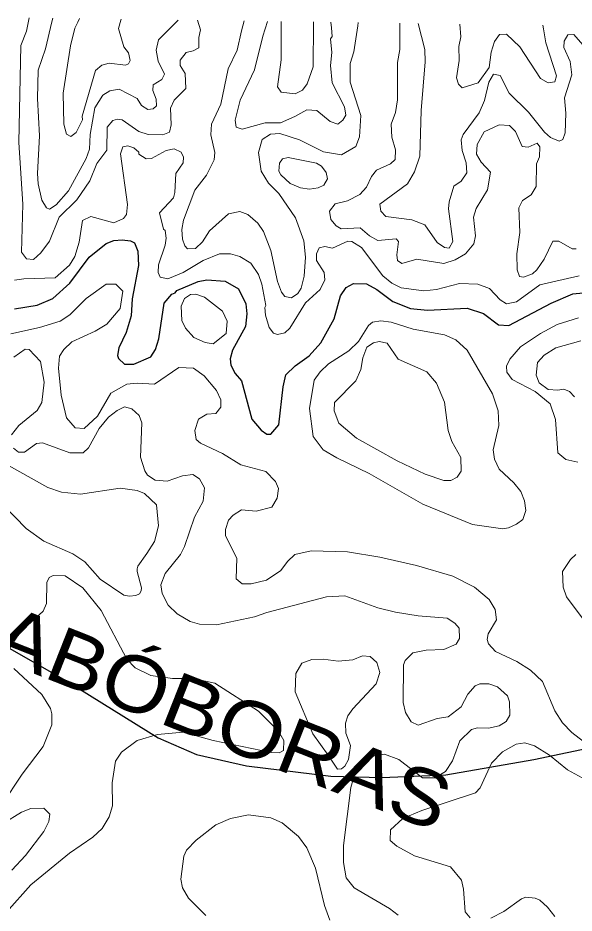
# Model space of a CAD drawing. Extents: x 763.2 to 816.8, y 7896.5 to 7952.7.
# Drawn here: x 774.248 to 776.64, y 7948.665 to 7952.514 of the extents above; entities that cross this region are included whole.
import ezdxf
from ezdxf.enums import TextEntityAlignment as Align

# ---------------------------------------------------------------- set-up
doc = ezdxf.new("R2010")
doc.units = 0
doc.header["$LTSCALE"] = 0.064
for name, color, linetype, lineweight in [('1', 7, 'Continuous', 25), ('2', 7, 'Continuous', 13), ('26', 7, 'Continuous', 25)]:
    doc.layers.add(name, color=color, linetype=linetype, lineweight=lineweight)

msp = doc.modelspace()

# ---------------------------------------------------------------- linework, layer by layer
at = {"layer": '1'}
for points in [[(774.2339, 7951.2633), (774.3307, 7951.2787), (774.398, 7951.307), (774.4715, 7951.3737), (774.5546, 7951.4846), (774.628, 7951.5442), (774.661, 7951.5566), (774.6964, 7951.5599), (774.7332, 7951.5549), (774.7492, 7951.5466), (774.7641, 7951.5112), (774.7677, 7951.4492)], [(774.7677, 7951.4492), (774.74, 7951.3061), (774.7349, 7951.233), (774.7138, 7951.1614), (774.6824, 7951.0949), (774.676, 7951.0628)], [(774.676, 7951.0628), (774.6812, 7951.05), (774.7072, 7951.0246), (774.7464, 7951.0257), (774.8201, 7951.057), (774.8398, 7951.0877), (774.8548, 7951.1344), (774.878, 7951.287), (774.9104, 7951.3261), (774.9253, 7951.3319), (774.9312, 7951.3416), (775.0242, 7951.3802), (775.0602, 7951.3871), (775.1396, 7951.3826), (775.1976, 7951.3484), (775.228, 7951.285), (775.2329, 7951.2421), (775.2277, 7951.1871), (775.1705, 7951.085), (775.1617, 7951.0476), (775.1636, 7951.0206), (775.1827, 7950.9848), (775.2094, 7950.9537), (775.254, 7950.7883), (775.2943, 7950.7418), (775.3184, 7950.7238), (775.3365, 7950.7235), (775.3707, 7950.7638), (775.3892, 7950.9281), (775.4007, 7950.9797), (775.44, 7951.0176), (775.5011, 7951.0609), (775.5517, 7951.1164), (775.6077, 7951.2206), (775.6361, 7951.319), (775.6596, 7951.3548), (775.6914, 7951.3724), (775.7471, 7951.3709), (775.7916, 7951.3463), (775.8613, 7951.2951), (775.9362, 7951.2643), (776.0103, 7951.2577), (776.1803, 7951.2656), (776.2511, 7951.2431), (776.3153, 7951.1938), (776.3596, 7951.192), (776.541, 7951.288), (776.6349, 7951.3277), (776.7095, 7951.3347)]]:
    msp.add_lwpolyline(points, dxfattribs=at)
at = {"layer": '2'}
for points in [[(774.2965, 7952.5138), (774.2936, 7952.4996), (774.2847, 7952.4563), (774.2617, 7952.3958), (774.2519, 7951.9778), (774.2698, 7951.7128), (774.2633, 7951.5071), (774.2859, 7951.4784), (774.3162, 7951.4746), (774.3475, 7951.5031), (774.3848, 7951.5535), (774.4264, 7951.6576), (774.5019, 7951.7315), (774.5579, 7951.8127), (774.5882, 7951.8876), (774.6309, 7951.9457), (774.6316, 7952.0442), (774.6563, 7952.0726), (774.6774, 7952.0791), (774.697, 7952.0759), (774.768, 7952.026), (774.8079, 7952.0132), (774.8721, 7952.0113), (774.901, 7952.0226), (774.9074, 7952.0547), (774.9046, 7952.1258), (774.9208, 7952.1598), (774.97, 7952.2104), (774.9683, 7952.2742), (774.9468, 7952.3093), (774.9455, 7952.3318), (774.9723, 7952.3652), (775.0027, 7952.3719), (775.0259, 7952.3848), (775.026, 7952.4294), (775.0337, 7952.4622), (775.0204, 7952.5034)], [(774.9377, 7952.5046), (774.8523, 7952.4197), (774.8436, 7952.375), (774.8517, 7952.3277), (774.8792, 7952.2724), (774.867, 7952.2496), (774.8301, 7952.2257), (774.8286, 7952.202), (774.8431, 7952.1638), (774.8446, 7952.1356), (774.8295, 7952.1226), (774.8071, 7952.1197), (774.7796, 7952.1373), (774.7618, 7952.1671), (774.6839, 7952.2074), (774.6439, 7952.2005), (774.613, 7952.1822), (774.5789, 7952.127), (774.5591, 7952.0119), (774.5556, 7951.9496), (774.5423, 7951.9095), (774.4661, 7951.7708), (774.4132, 7951.7101), (774.3838, 7951.6915), (774.3721, 7951.6966), (774.3517, 7951.73), (774.3354, 7951.7998), (774.3323, 7951.8443), (774.342, 7952.0069), (774.3323, 7952.1671), (774.3357, 7952.2887), (774.3669, 7952.3808), (774.3948, 7952.4968), (774.3985, 7952.5123)], [(774.514, 7952.5107), (774.5061, 7952.4948), (774.4936, 7952.4697), (774.4739, 7952.3939), (774.4424, 7952.1901), (774.4462, 7952.0575), (774.4577, 7952.0134), (774.4758, 7952.004), (774.4986, 7952.021), (774.526, 7952.0753), (774.5249, 7952.0913), (774.5826, 7952.2882), (774.61, 7952.3108), (774.6412, 7952.3191), (774.7106, 7952.3099), (774.7244, 7952.3161), (774.7318, 7952.3309), (774.7247, 7952.3639), (774.7036, 7952.3892), (774.6808, 7952.4688), (774.6906, 7952.5034), (774.6919, 7952.5081)], [(775.2207, 7952.5005), (775.2104, 7952.4576), (775.1906, 7952.3749), (775.1525, 7952.2946), (775.1209, 7952.1428), (775.0807, 7952.057), (775.0784, 7952.0105), (775.0948, 7951.9358), (775.093, 7951.9036), (775.059, 7951.8383), (775.0086, 7951.7732), (774.9603, 7951.6445), (774.9536, 7951.6037), (774.9557, 7951.5618), (774.966, 7951.5334), (774.9777, 7951.5212), (775.012, 7951.5224), (775.0419, 7951.5516), (775.0729, 7951.5988), (775.1534, 7951.672), (775.2031, 7951.6813), (775.2367, 7951.668), (775.2805, 7951.6307), (775.3048, 7951.5951), (775.3358, 7951.5145), (775.3653, 7951.3799), (775.382, 7951.3345), (775.3967, 7951.3166), (775.4245, 7951.3102), (775.4519, 7951.3291), (775.466, 7951.3516), (775.4791, 7951.4033), (775.4844, 7951.4849), (775.4775, 7951.5558), (775.4424, 7951.6549), (775.3707, 7951.7589), (775.3262, 7951.8038), (775.2948, 7951.8555), (775.2823, 7951.935), (775.2981, 7951.9907), (775.3347, 7952.0134), (775.3742, 7952.0168), (775.4591, 7951.9891), (775.5628, 7951.9384), (775.6401, 7951.9251), (775.701, 7951.9612), (775.7176, 7952.0028), (775.7226, 7952.0944), (775.677, 7952.2373), (775.6766, 7952.3182), (775.6931, 7952.3676), (775.7096, 7952.4804), (775.7115, 7952.4934)], [(775.594, 7952.4951), (775.5964, 7952.4705), (775.6, 7952.4336), (775.5928, 7952.4241), (775.5978, 7952.3648), (775.5927, 7952.3095), (775.5996, 7952.2349), (775.6528, 7952.1317), (775.6582, 7952.0954), (775.645, 7952.074), (775.6236, 7952.0564), (775.5912, 7952.0679), (775.534, 7952.1151), (775.4906, 7952.1187), (775.4399, 7952.0893), (775.3769, 7952.0629), (775.3111, 7952.0627), (775.2127, 7952.0351), (775.1872, 7952.0435), (775.1821, 7952.0746), (775.2043, 7952.16), (775.2655, 7952.2907), (775.3018, 7952.4353), (775.3218, 7952.499)], [(775.3809, 7952.4982), (775.3809, 7952.466), (775.3807, 7952.3334), (775.3648, 7952.2171), (775.3811, 7952.1946), (775.441, 7952.1879), (775.4726, 7952.2031), (775.4921, 7952.2303), (775.5183, 7952.3041), (775.5189, 7952.487), (775.5189, 7952.4962)], [(775.8905, 7952.4908), (775.8902, 7952.3775), (775.8804, 7952.3224), (775.8803, 7952.1617), (775.8721, 7952.1073), (775.8541, 7952.0566), (775.8565, 7952.0005), (775.872, 7951.9469), (775.8703, 7951.9044), (775.8511, 7951.8864), (775.7906, 7951.8594), (775.7687, 7951.8321), (775.7471, 7951.7855), (775.7193, 7951.7542), (775.6654, 7951.7272), (775.6122, 7951.7139), (775.5882, 7951.6823), (775.5945, 7951.6474), (775.6163, 7951.6204), (775.6384, 7951.607), (775.7207, 7951.6107), (775.7606, 7951.5764), (775.7958, 7951.557), (775.8746, 7951.5639), (775.8851, 7951.552), (775.8772, 7951.4954), (775.8804, 7951.4706), (775.8996, 7951.4585), (775.9645, 7951.4761), (776.0796, 7951.4583), (776.129, 7951.4739), (776.1731, 7951.4999), (776.2089, 7951.542), (776.2155, 7951.5762), (776.2075, 7951.657), (776.2193, 7951.6937), (776.2679, 7951.7747), (776.2806, 7951.8499), (776.2409, 7951.8932), (776.2199, 7951.9279), (776.2231, 7951.969), (776.2529, 7952.0234), (776.3175, 7952.0547), (776.3629, 7952.0512), (776.3888, 7952.025), (776.4164, 7951.9613), (776.4422, 7951.958), (776.4812, 7951.9754), (776.4932, 7951.9602), (776.4916, 7951.9159), (776.4787, 7951.887), (776.4768, 7951.7893), (776.4551, 7951.7525), (776.4185, 7951.7281), (776.4031, 7951.6979), (776.4062, 7951.5912), (776.3932, 7951.4992), (776.3949, 7951.4302), (776.4053, 7951.4019), (776.422, 7951.399), (776.4614, 7951.4135), (776.4802, 7951.4304), (776.5114, 7951.4763), (776.5485, 7951.5532), (776.5739, 7951.5532), (776.6313, 7951.5206), (776.6493, 7951.5208)], [(776.7676, 7952.2955), (776.6383, 7952.4426), (776.6129, 7952.4415), (776.598, 7952.4131), (776.5954, 7952.3863), (776.6234, 7952.3269), (776.6298, 7952.2696), (776.599, 7952.1702), (776.605, 7952.104), (776.6015, 7952.0203), (776.5919, 7951.9911), (776.5755, 7951.9845), (776.5382, 7951.9993), (776.5129, 7952.0221), (776.4447, 7952.1085), (776.3608, 7952.1905), (776.3225, 7952.2661), (776.294, 7952.2722), (776.2736, 7952.2377), (776.2548, 7952.1584), (776.232, 7952.1061), (776.1632, 7952.0118), (776.155, 7951.9889), (776.1581, 7951.9436), (776.176, 7951.891), (776.1795, 7951.8474), (776.1551, 7951.8123), (776.1235, 7951.791), (776.1023, 7951.7227), (776.0994, 7951.6923), (776.1187, 7951.5529), (776.1031, 7951.524), (776.0833, 7951.5262), (776.0515, 7951.5485), (775.9978, 7951.6243), (775.9428, 7951.6454), (775.831, 7951.6599), (775.8085, 7951.6828), (775.8051, 7951.7126), (775.9241, 7951.8011), (775.9545, 7951.8516), (775.9772, 7951.92), (775.9823, 7952.1154), (776.0003, 7952.3249), (775.9984, 7952.3783), (775.9695, 7952.4896)], [(776.1489, 7952.487), (776.153, 7952.4327), (776.145, 7952.3902), (776.1466, 7952.3309), (776.1338, 7952.2558), (776.1432, 7952.2295), (776.1591, 7952.2129), (776.2279, 7952.2353), (776.2746, 7952.3004), (776.2831, 7952.3669), (776.298, 7952.4129), (776.3194, 7952.442), (776.3492, 7952.4435), (776.4067, 7952.3893), (776.4955, 7952.2533), (776.5281, 7952.2341), (776.5574, 7952.2393), (776.5639, 7952.2651), (776.5179, 7952.4071), (776.5083, 7952.4672), (776.506, 7952.4819)], [(775.5683, 7951.5317), (775.5435, 7951.5249), (775.5322, 7951.4999), (775.532, 7951.4709), (775.5649, 7951.419), (775.568, 7951.3882), (775.5484, 7951.3454), (775.4858, 7951.2883), (775.4174, 7951.1792), (775.396, 7951.16), (775.365, 7951.1525), (775.3479, 7951.1579), (775.3293, 7951.1823), (775.313, 7951.2353), (775.3102, 7951.2692), (775.315, 7951.2769), (775.2972, 7951.3696), (775.2823, 7951.4099), (775.2504, 7951.46), (775.2033, 7951.4877), (775.1624, 7951.4993), (775.1157, 7951.4994), (775.0455, 7951.4712), (774.9588, 7951.4197), (774.8928, 7951.3924), (774.8597, 7951.3998), (774.8517, 7951.4185), (774.8532, 7951.4526), (774.8822, 7951.5365), (774.8862, 7951.5671), (774.8811, 7951.6004), (774.8746, 7951.6053), (774.8566, 7951.6757), (774.9169, 7951.7401), (774.9239, 7951.7628), (774.9273, 7951.8443), (774.9589, 7951.8914), (774.96, 7951.9156), (774.95, 7951.9361), (774.9199, 7951.951), (774.8864, 7951.9439), (774.8233, 7951.909), (774.8, 7951.9085), (774.7684, 7951.928), (774.7687, 7951.9366), (774.7468, 7951.9557), (774.7207, 7951.9643), (774.699, 7951.9591), (774.689, 7951.9289), (774.7201, 7951.7122), (774.7148, 7951.668), (774.7028, 7951.6516), (774.6616, 7951.6327), (774.5625, 7951.6602), (774.5267, 7951.6422), (774.5115, 7951.5492), (774.493, 7951.4887), (774.4707, 7951.4506), (774.409, 7951.3965), (774.2738, 7951.3924), (774.2336, 7951.3858)], [(775.8171, 7951.405), (775.7259, 7951.527), (775.6846, 7951.5527), (775.6676, 7951.5533), (775.6007, 7951.5241), (775.5683, 7951.5317)], [(776.6614, 7951.4052), (776.4929, 7951.3663), (776.3918, 7951.2933), (776.3498, 7951.284), (776.3229, 7951.3012), (776.276, 7951.3498), (776.2258, 7951.3693), (776.1473, 7951.3726), (776.049, 7951.3459), (775.9945, 7951.34), (775.8971, 7951.3532), (775.857, 7951.3736), (775.8171, 7951.405)], [(774.2176, 7951.1554), (774.3412, 7951.1827), (774.4295, 7951.2093), (774.4714, 7951.2372), (774.5415, 7951.3074), (774.6283, 7951.3691), (774.6696, 7951.3693), (774.6999, 7951.3384), (774.6877, 7951.2639), (774.6302, 7951.1974), (774.5801, 7951.1664), (774.4803, 7951.1211), (774.4457, 7951.0883), (774.4278, 7951.0597), (774.4227, 7951.0081), (774.4342, 7950.8918), (774.4573, 7950.7946), (774.4947, 7950.7519), (774.5338, 7950.7486), (774.5903, 7950.8012), (774.6479, 7950.9008), (774.7175, 7950.9389), (774.7613, 7950.9438), (774.8355, 7950.9393), (774.9405, 7951.0109), (775.0028, 7951.0076), (775.0493, 7950.9744), (775.103, 7950.9123), (775.1211, 7950.8724), (775.1211, 7950.8396), (775.0995, 7950.8127), (775.0614, 7950.8103), (775.0257, 7950.7887), (775.0094, 7950.7393), (775.0146, 7950.7008), (775.0334, 7950.6853), (775.1277, 7950.6413), (775.2073, 7950.5919), (775.314, 7950.5642), (775.3557, 7950.5202), (775.369, 7950.4901), (775.3638, 7950.4494), (775.3403, 7950.411), (775.2731, 7950.3933), (775.2104, 7950.3993), (775.1744, 7950.376), (775.1546, 7950.3542), (775.1412, 7950.314), (775.1409, 7950.2873), (775.1902, 7950.1904), (775.1868, 7950.1027), (775.2132, 7950.0812), (775.2519, 7950.081), (775.3177, 7950.0971), (775.3795, 7950.1374), (775.4078, 7950.1765), (775.4397, 7950.2068), (775.509, 7950.2222), (775.666, 7950.2189), (775.8042, 7950.196), (775.9619, 7950.1599), (776.119, 7950.1142), (776.2117, 7950.0665), (776.2752, 7950.0129), (776.3004, 7949.9705), (776.3058, 7949.9252), (776.2709, 7949.8657), (776.2668, 7949.842), (776.2717, 7949.823), (776.3025, 7949.7895), (776.3937, 7949.747), (776.4529, 7949.7091), (776.5039, 7949.6613), (776.5567, 7949.535), (776.5906, 7949.4832), (776.6309, 7949.4422), (776.7185, 7949.3742)], [(776.6588, 7951.2245), (776.568, 7951.1953), (776.496, 7951.1576), (776.4097, 7951.0998), (776.3632, 7951.0465), (776.349, 7951.016), (776.3505, 7950.9907), (776.3735, 7950.9588), (776.472, 7950.9075), (776.5375, 7950.8549), (776.5605, 7950.7866), (776.5701, 7950.6432), (776.6042, 7950.6149), (776.656, 7950.6037)], [(776.6686, 7951.1259), (776.5618, 7951.0949), (776.5119, 7951.0637), (776.4823, 7951.0329), (776.4771, 7950.9781), (776.4896, 7950.9447), (776.5286, 7950.9159), (776.57, 7950.9126), (776.5956, 7950.9172), (776.6203, 7950.9069), (776.6422, 7950.8852)], [(774.2312, 7951.0547), (774.2792, 7951.0895), (774.2965, 7951.0879), (774.345, 7951.037), (774.3616, 7950.947), (774.3515, 7950.861), (774.3306, 7950.8258), (774.253, 7950.7608), (774.2209, 7950.7216)], [(774.2293, 7950.6637), (774.2517, 7950.6463), (774.2766, 7950.6467), (774.3278, 7950.6833), (774.3541, 7950.6874), (774.4723, 7950.6433), (774.5288, 7950.6432), (774.5524, 7950.666), (774.5978, 7950.7486), (774.638, 7950.7974), (774.6748, 7950.8257), (774.7073, 7950.8412), (774.7389, 7950.8329), (774.7696, 7950.8049), (774.7808, 7950.7728), (774.7761, 7950.6257), (774.7939, 7950.5664), (774.8055, 7950.5479), (774.8384, 7950.5268), (774.8909, 7950.5214), (774.9568, 7950.5443), (775, 7950.5506), (775.0297, 7950.5323), (775.0502, 7950.4936), (775.045, 7950.4362)], [(774.0143, 7950.6972), (774.377, 7950.4943), (774.4352, 7950.4744), (774.5177, 7950.4656), (774.6879, 7950.4916), (774.7609, 7950.4816), (774.7926, 7950.4685), (774.8449, 7950.4203), (774.8532, 7950.3298), (774.836, 7950.2621), (774.8027, 7950.2105), (774.7638, 7950.1566), (774.7616, 7950.1456), (774.7617, 7950.1341), (774.7806, 7950.0638), (774.7791, 7950.0505), (774.7713, 7950.0377), (774.755, 7950.0298), (774.7289, 7950.027), (774.7044, 7950.0316), (774.6024, 7950.1012), (774.5357, 7950.175), (774.485, 7950.209), (774.3596, 7950.2638), (774.2834, 7950.3185), (774.1865, 7950.4189)], [(775.045, 7950.4362), (775.0076, 7950.3676), (774.9651, 7950.241), (774.9476, 7950.2064), (774.8812, 7950.1253), (774.8632, 7950.076)], [(776.647, 7950.2062), (776.6244, 7950.1856), (776.5904, 7950.1344), (776.5933, 7950.066), (776.6071, 7950.0252), (776.7858, 7949.7867)], [(774.1992, 7948.6692), (774.3038, 7948.787), (774.4704, 7948.9223), (774.571, 7948.992), (774.6104, 7949.0282), (774.6408, 7949.0795), (774.6558, 7949.1255), (774.6532, 7949.2258), (774.6677, 7949.3177), (774.6944, 7949.3567), (774.7609, 7949.4076), (774.8484, 7949.4334), (774.9585, 7949.4432), (775.0882, 7949.4072), (775.3375, 7949.3553), (775.3724, 7949.3545), (775.3908, 7949.3642), (775.3913, 7949.4072), (775.3696, 7949.4478), (775.2827, 7949.5331), (775.0954, 7949.6533), (775.0021, 7949.6732), (774.9132, 7949.6731), (774.8194, 7949.6865), (774.753, 7949.7194), (774.7167, 7949.7561), (774.6059, 7949.9662), (774.5278, 7950.0628), (774.4513, 7950.115), (774.3998, 7950.1168), (774.383, 7950.1078), (774.3735, 7950.0858), (774.3718, 7949.9954), (774.3569, 7949.9633), (774.2562, 7949.8716), (774.2111, 7949.8017)], [(774.8632, 7950.076), (774.8683, 7950.0392), (774.8949, 7949.9885), (774.9338, 7949.9512), (774.989, 7949.9186), (775.0298, 7949.9068), (775.1028, 7949.9037), (775.2664, 7949.9381), (775.319, 7949.9577), (775.5748, 7950.0249), (775.6543, 7950.0284), (775.7956, 7949.9772), (775.8715, 7949.9582), (775.9699, 7949.9437), (776.0946, 7949.9327), (776.1278, 7949.9122), (776.1463, 7949.89), (776.1479, 7949.8456), (776.1323, 7949.8206), (776.0801, 7949.7984), (776.0047, 7949.7948), (775.9469, 7949.7836), (775.9134, 7949.7506), (775.9067, 7949.7326), (775.9051, 7949.5699), (775.9152, 7949.5273), (775.9396, 7949.4879), (775.9697, 7949.4729), (776.0507, 7949.5021), (776.0992, 7949.5086), (776.1543, 7949.5512), (776.1832, 7949.6066), (776.2151, 7949.6416), (776.2351, 7949.6502), (776.2741, 7949.6503), (776.311, 7949.6372), (776.3536, 7949.5987), (776.3619, 7949.5738), (776.3634, 7949.5163), (776.3485, 7949.489), (776.3184, 7949.4695), (776.2722, 7949.4599), (776.2244, 7949.4615), (776.199, 7949.4542), (776.1493, 7949.4058), (776.117, 7949.32), (776.0871, 7949.2738), (776.0415, 7949.2471), (775.988, 7949.2461), (775.8866, 7949.3257), (775.8252, 7949.3477), (775.7821, 7949.3411), (775.7424, 7949.3183), (775.6968, 7949.2647), (775.6802, 7949.2057), (775.6487, 7948.9551), (775.6487, 7948.8829), (775.6596, 7948.817), (775.6944, 7948.773), (775.8469, 7948.6844), (775.8836, 7948.656)], [(774.2309, 7949.7172), (774.3508, 7949.6054), (774.3879, 7949.5442), (774.3949, 7949.5215), (774.3947, 7949.4739), (774.3566, 7949.3818), (774.2673, 7949.2629), (774.1787, 7949.1307)], [(776.69, 7949.2387), (776.6118, 7949.2806), (776.5338, 7949.3434), (776.4694, 7949.3837), (776.4288, 7949.3972), (776.3905, 7949.3907), (776.3328, 7949.3577), (776.2856, 7949.3096), (776.236, 7949.2031), (776.2163, 7949.1827), (775.985, 7949.1061)], [(774.2222, 7948.85), (774.2818, 7948.913), (774.3602, 7949.0153), (774.3819, 7949.0584), (774.3863, 7949.0908), (774.3604, 7949.1158), (774.3034, 7949.1146), (774.2646, 7949.0987), (774.1849, 7949.0508)], [(775.985, 7949.1061), (775.9039, 7949.0715), (775.8512, 7949.023), (775.8494, 7948.9769), (775.8773, 7948.9529), (775.9534, 7948.9106)], [(775.5894, 7948.6351), (775.567, 7948.6975), (775.5281, 7948.8579), (775.4907, 7948.9453), (775.4546, 7948.9946), (775.3854, 7949.0527), (775.336, 7949.0746), (775.2394, 7949.0882), (775.1621, 7949.0722), (775.1002, 7949.0446), (775.0148, 7948.9786), (774.9738, 7948.935), (774.9625, 7948.9098), (774.9487, 7948.8112), (774.9565, 7948.7741), (774.9815, 7948.7298), (775.0565, 7948.655)], [(775.9534, 7948.9106), (776.1091, 7948.8636), (776.1563, 7948.8073), (776.1647, 7948.7685), (776.1711, 7948.6702), (776.1925, 7948.6441)], [(776.2822, 7948.6432), (776.3384, 7948.6712), (776.4145, 7948.7266), (776.4325, 7948.7332), (776.472, 7948.7299), (776.4926, 7948.7212), (776.5262, 7948.6908), (776.5566, 7948.6497)]]:
    msp.add_lwpolyline(points, dxfattribs=at)
for points in [[(775.4639, 7951.7835), (775.4198, 7951.802), (775.3792, 7951.8395), (775.3711, 7951.8555), (775.3737, 7951.8893), (775.3864, 7951.9085), (775.4109, 7951.9132), (775.532, 7951.8887), (775.5537, 7951.8768), (775.5743, 7951.8497), (775.5797, 7951.822), (775.5642, 7951.7949), (775.5401, 7951.7838), (775.5019, 7951.777)], [(774.9694, 7951.1802), (774.9536, 7951.2124), (774.9503, 7951.2746), (774.9648, 7951.3078), (774.9905, 7951.325), (775.0131, 7951.3263), (775.0503, 7951.3133), (775.1286, 7951.2526), (775.1488, 7951.21), (775.1439, 7951.1575), (775.0884, 7951.1131), (775.0536, 7951.1176), (775.0052, 7951.1394)], [(776.3159, 7950.7611), (776.3141, 7950.8246), (776.2895, 7950.8977), (776.1798, 7951.085), (776.1317, 7951.1294), (776.0835, 7951.151), (775.9476, 7951.1751), (775.8541, 7951.205), (775.8088, 7951.2115), (775.7733, 7951.2053), (775.7556, 7951.1917), (775.7129, 7951.1219), (775.6709, 7951.083), (775.5835, 7951.0265), (775.5478, 7950.9924), (775.5223, 7950.9561), (775.5026, 7950.8352), (775.5185, 7950.7136), (775.561, 7950.6567), (775.6193, 7950.6224), (775.7594, 7950.5555), (775.9902, 7950.4237), (776.2031, 7950.3355), (776.3333, 7950.3177), (776.3584, 7950.3212), (776.3931, 7950.3366), (776.4193, 7950.3575), (776.4319, 7950.3959), (776.4262, 7950.4369), (776.4108, 7950.4776), (776.381, 7950.5153), (776.3183, 7950.5735), (776.2974, 7950.6164), (776.2927, 7950.6563)], [(776.083, 7950.8622), (776.0483, 7950.9431), (776.0074, 7950.9925), (775.8829, 7951.0473), (775.8362, 7951.1157), (775.8026, 7951.1226), (775.7781, 7951.1175), (775.7493, 7951.098), (775.7311, 7951.0529), (775.7224, 7951.0023), (775.7011, 7950.9537), (775.6094, 7950.8606), (775.6077, 7950.8242), (775.6288, 7950.7711), (775.7051, 7950.7074), (775.8798, 7950.6088), (775.9994, 7950.5524), (776.0803, 7950.525), (776.11, 7950.5247), (776.1376, 7950.5386), (776.1541, 7950.5644), (776.1533, 7950.6236), (776.1144, 7950.6926), (776.099, 7950.7399)], [(775.6573, 7949.4816), (775.667, 7949.5137), (775.6883, 7949.5436), (775.7896, 7949.6512), (775.8048, 7949.6988), (775.7915, 7949.7424), (775.7625, 7949.7681), (775.7299, 7949.7705), (775.6884, 7949.754), (775.626, 7949.7475), (775.5609, 7949.7571), (775.5123, 7949.7555), (775.4697, 7949.7389), (775.4433, 7949.6947), (775.4402, 7949.6167), (775.516, 7949.4355), (775.5829, 7949.3446), (775.623, 7949.284), (775.6397, 7949.2852), (775.6538, 7949.2962), (775.6705, 7949.3255), (775.6782, 7949.3852), (775.6585, 7949.439)]]:
    msp.add_lwpolyline(points, close=True, dxfattribs=at)
at = {"layer": '26'}
msp.add_lwpolyline([(771.0421, 7950.2756), (771.5707, 7950.4081), (771.8675, 7950.4081), (772.1862, 7950.3587), (772.7633, 7950.2433), (773.2359, 7950.1278), (773.769, 7949.9795), (774.1427, 7949.8421), (774.4614, 7949.6607), (774.8516, 7949.4189), (775.0165, 7949.3475), (775.2308, 7949.298), (775.5935, 7949.254), (775.8133, 7949.2485), (776.0881, 7949.2595), (776.4673, 7949.3255), (776.7531, 7949.3859), (777.2642, 7949.5343), (777.4895, 7949.6058), (777.7258, 7949.7322), (777.8687, 7949.8366), (778.385, 7950.2639)], dxfattribs=at)

# ---------------------------------------------------------------- texts
at = {"layer": '26', "width": 1.15}
msp.add_text('SA. DAS ABÓBORAS', height=0.24, rotation=338.475, dxfattribs=at).set_placement((774.3602, 7949.6776), align=Align.CENTER)

doc.saveas('drawing.dxf')
